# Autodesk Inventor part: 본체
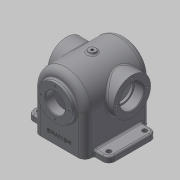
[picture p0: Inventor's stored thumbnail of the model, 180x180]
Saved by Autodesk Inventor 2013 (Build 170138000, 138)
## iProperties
Created: 2019-05
Part Number: 본체
Material: 일반
Document SubType Name: Modeling
Designer: mduedu
Density: 1 g/cm^3
Author: mduedu
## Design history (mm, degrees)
sketch "스케치1"
  geometry: L1 (-55, 0)-(55, 0); L2 (55, 0)-(55, 110); L3 (55, 110)-(-55, 110); L4 (-55, 110)-(-55, 0); 2 further points
  constraints: 8 end point, 2 parallel, 1 coincident, 1 horizontal, 1 midpoint, 1 perpendicular
  dimensions: "d0" = 110 distance of L3.end L1.start; "d2" = 110 distance of L2.end L3.end
extrude "돌출1" new body sketch "스케치1" stored distance "d3" = 86; taper "d4" = 0 deg
fillet "모깎기1"
fillet "모깎기2" dims "d5" = 11
feature "쉘1" dims "d6" = 8
sketch "스케치2"
  geometry: C1 r 29 at (-32, 67); A1 r 43 centre (-32, 67) between (11, 67) and (-75, 67) reference; 1 further point
  constraints: 1 centre point, 1 coincident
  dimensions: "d7" = 58 diameter of C1
extrude "돌출2" join sketch "스케치2" distance "d8" = 7; taper "d9" = 0 deg
fillet "모깎기3" dims "d10" = 3
hole "구멍1" diameter "d13" = 33; stored, may be unused: countersink angle "d17" = 90 deg, drill point angle "d19" = 118 deg; dims "d11" = 10, "d12" = 10, "d14" = 6, "d15" = 4, "d16" = 2, "d18" = 8
node "작업 평면1"
sketch "스케치3"
  geometry: L1 (18, -29)-(18, 29) reference; L2 (-99, 0)-(-99, 32) reference; C1 r 31 at (-56, 0); 2 further points
  constraints: 1 centre point, 1 horizontal alignment, 1 midpoint
  dimensions: "d21" = 62 diameter of C1; "d24" = 43 distance from line of C1.centre L2
extrude "돌출3" join sketch "스케치3" stored distance "d25" = 5; taper "d26" = 0 deg
hole "구멍2" diameter "d29" = 40; stored, may be unused: countersink angle "d33" = 90 deg, drill point angle "d35" = 0 deg; dims "d27" = 10, "d28" = 10, "d30" = 6, "d31" = 4, "d32" = 2, "d34" = 16
hole "구멍3" diameter "d38" = 35; stored, may be unused: countersink angle "d42" = 90 deg, drill point angle "d44" = 0 deg; dims "d36" = 10, "d37" = 10, "d39" = 6, "d40" = 4, "d41" = 2, "d43" = 16
fillet "모깎기4" dims "d45" = 3
chamfer "모따기1" distance "d46" = 1; stored, may be unused: second distance "d47" = 2, angle "d48" = 45 deg
chamfer "모따기2" distance "d49" = 1; stored, may be unused: second distance "d50" = 2, angle "d51" = 45 deg
fillet "모깎기5" dims "d52" = 0.3
node "작업 평면2"
sketch "스케치4"
  geometry: L1 (11, 75)-(11, 11) reference; C1 r 6 at (-44, 43); 1 further point
  constraints: 1 centre point, 1 coincident
  dimensions: "d54" = 12 diameter of C1; "d67" = 55 distance from line of point (-44, 43) L1 (derived)
extrude "돌출4" join sketch "스케치4" stored distance "d55" = 5; taper "d56" = 0 deg
hole "구멍4" diameter "d59" = 4.134; stored, may be unused: countersink angle "d63" = 90 deg, drill point angle "d65" = 0 deg; dims "d57" = 10, "d58" = 10, "d60" = 6, "d61" = 4, "d62" = 2, "d64" = 16
fillet "모깎기6" dims "d66" = 3
sketch "스케치5"
  geometry: L1 (47, -32)-(47, 32) reference; L2 (44, 35)-(-44, 35) reference; L3 (-47, 32)-(-47, -32) reference; L4 (-44, -35)-(44, -35) reference; L5 (-44, -43)-(44, -43) reference; L6 (-55, -32)-(-55, 32) reference; L7 (44, 43)-(-44, 43) reference; L8 (55, 32)-(55, -32) reference; L9 (40, 43)-(-40, 43); L10 (-40, 43)-(-40, 68); L11 (-40, 68)-(40, 68); L12 (40, 68)-(40, 43); A1 r 3 centre (44, -32) between (44, -35) and (47, -32) reference; A2 r 3 centre (44, 32) between (47, 32) and (44, 35) reference; A3 r 3 centre (-44, 32) between (-44, 35) and (-47, 32) reference; A4 r 3 centre (-44, -32) between (-47, -32) and (-44, -35) reference; A5 r 11 centre (44, -32) between (44, -43) and (55, -32) reference; A6 r 11 centre (-44, -32) between (-55, -32) and (-44, -43) reference; A7 r 11 centre (-44, 32) between (-44, 43) and (-55, 32) reference; A8 r 11 centre (44, 32) between (55, 32) and (44, 43) reference; 1 further point
  constraints: 8 end point, 2 parallel, 1 horizontal, 1 perpendicular, 1 point on line
  dimensions: "d68" = 15 distance between parallel lines of L12 L8; "d71" = 80 distance of L10.end L11.end; "d72" = 25 distance between parallel lines of L11 L7
extrude "돌출5" join sketch "스케치5" distance "d73" = 10; taper "d74" = 0 deg
fillet "모깎기7" dims "d76" = 10
sketch "스케치6"
  geometry: L1 (-40, -43)-(-40, -58) reference; L2 (-30, -68)-(30, -68) reference; L3 (40, -58)-(40, -43) reference; L4 (-40, -43)-(40, -43) reference; C1 r 4 at (-30, -58); C2 r 4 at (30, -58); A1 r 10 centre (30, -58) between (30, -68) and (40, -58) reference; A2 r 10 centre (-30, -58) between (-40, -58) and (-30, -68) reference; 1 further point
  constraints: 2 centre point, 2 coincident, 1 equal radius
  dimensions: "d77" = 8 diameter of C1
extrude "돌출6" cut sketch "스케치6" stored distance "d78" = 10; taper "d79" = 0 deg
fillet "모깎기8" dims "d80" = 3
fillet "모깎기9" dims "d81" = 3
fillet "모깎기10" dims "d82" = 3
fillet "모깎기11" dims "d83" = 3
sketch "스케치7"
  geometry: L1 (64, 0)-(0, 0) reference; 4 further points
  constraints: 2 midpoint, 2 vertical alignment, 1 other
  dimensions: "d85" = 15 distance of point (32, 15) point (32, 0)
feature "엠보싱1" sketch "스케치7" dims "d7" = 58, "d86" = 0.5, "d87" = 0
sketch "스케치8"
  geometry: 4 further points
  constraints: 4 other
hole "구멍5" sketch "스케치8" at (0, 24), (-24, 0), (0, -24), (24, 0) diameter "d88" = 3.242; stored, may be unused: countersink angle "d92" = 90 deg, drill point angle "d94" = 120 deg; dims "d89" = 8, "d90" = 4, "d91" = 2, "d93" = 10
sketch "스케치9"
  geometry: 4 further points
  constraints: 4 other
hole "구멍7" sketch "스케치9" at (-26, 0), (0, -26), (26, 0), (0, 26) diameter "d95" = 3.242; stored, may be unused: countersink angle "d99" = 90 deg, drill point angle "d101" = 120 deg; dims "d96" = 8, "d97" = 4, "d98" = 2, "d100" = 10
sketch "스케치10"
  geometry: 4 further points
  constraints: 4 other
hole "구멍9" sketch "스케치10" at (0, -26), (26, 0), (-26, 0), (0, 26) diameter "d102" = 3.242; stored, may be unused: countersink angle "d106" = 90 deg, drill point angle "d108" = 120 deg; dims "d103" = 8, "d104" = 4, "d105" = 2, "d107" = 10
node "솔리드1"
mirror "대칭1"
mirror "대칭2"
node "투영된 루프1"
node "투영된 루프2"
other parameters: "d53" = -113
